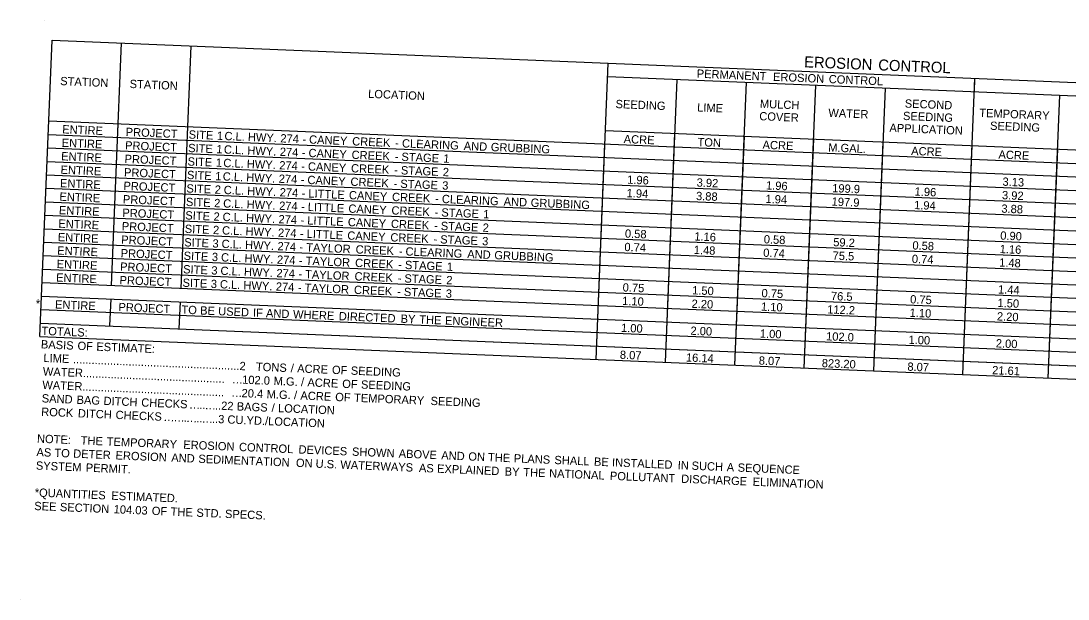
# Model space of a CAD drawing. Extents: x 1164179 to 1171425, y 1655958 to 1657208.
# Drawn here: x 1166097 to 1166854, y 1656742 to 1657160 of the extents above; entities that cross this region are included whole.
import ezdxf

# ---------------------------------------------------------------- set-up
doc = ezdxf.new("R2010")
doc.units = 0
doc.layers.add('Default', color=7, linetype='Continuous')

msp = doc.modelspace()

# ---------------------------------------------------------------- linework, layer by layer
at = {"layer": 'Default'}
for p, q in [((1166114.2, 1657160.31), (1166114.2, 1657160.31)), ((1166110.61, 1656932.12), (1166119.48, 1657146.43)), ((1166110.61, 1656932.12), (1166119.48, 1657146.43)), ((1166119.48, 1657146.43), (1167314.3, 1657097.01)), ((1166162.4, 1656969.01), (1166169.65, 1657144.36)), ((1166212.57, 1656966.93), (1166219.82, 1657142.28)), ((1166512.46, 1656915.49), (1166521.32, 1657129.81)), ((1166520.92, 1657120.07), (1167313.89, 1657087.27)), ((1166562.63, 1656913.42), (1166571.09, 1657117.99)), ((1166612.8, 1656911.34), (1166621.26, 1657115.92)), ((1166777.43, 1656904.53), (1166786.3, 1657118.85)), ((1166785.89, 1657109.11), (1166786.3, 1657118.85)), ((1166662.97, 1656909.27), (1166671.43, 1657113.84)), ((1166713.14, 1656907.19), (1166721.6, 1657111.77)), ((1166839.29, 1656901.97), (1166847.75, 1657106.55)), ((1166117.06, 1657087.98), (1167311.88, 1657038.56)), ((1166162.4, 1656969.01), (1166167.23, 1657085.91)), ((1166116.66, 1657078.24), (1167311.47, 1657028.82)), ((1166212.57, 1656966.93), (1166217.4, 1657083.83)), ((1166519.31, 1657081.1), (1167186.13, 1657053.52)), ((1166562.63, 1656913.42), (1166569.48, 1657079.03)), ((1166612.8, 1656911.34), (1166619.65, 1657076.95)), ((1166512.46, 1656915.49), (1166518.91, 1657071.36)), ((1166662.97, 1656909.27), (1166669.82, 1657074.88)), ((1166713.14, 1656907.19), (1166719.99, 1657072.8)), ((1166777.43, 1656904.53), (1166784.28, 1657070.14)), ((1166116.26, 1657068.5), (1167311.07, 1657019.07)), ((1166839.29, 1656901.97), (1166846.14, 1657067.58)), ((1166115.85, 1657058.76), (1167310.67, 1657009.33)), ((1166115.45, 1657049.02), (1167310.27, 1656999.59)), ((1166115.05, 1657039.28), (1167309.86, 1656989.85)), ((1166114.64, 1657029.53), (1167309.46, 1656980.11)), ((1166114.24, 1657019.79), (1167309.06, 1656970.37)), ((1166113.84, 1657010.05), (1167308.65, 1656960.62)), ((1166113.44, 1657000.31), (1167308.25, 1656950.88)), ((1166113.03, 1656990.57), (1167307.85, 1656941.14)), ((1166112.63, 1656980.83), (1167307.44, 1656931.4)), ((1166112.23, 1656971.08), (1167307.04, 1656921.66)), ((1166111.82, 1656961.34), (1167306.64, 1656911.92)), ((1166161.19, 1656939.78), (1166161.99, 1656959.27)), ((1166161.19, 1656939.78), (1166161.99, 1656959.27)), ((1166211.36, 1656937.71), (1166212.16, 1656957.19)), ((1166211.36, 1656937.71), (1166212.16, 1656957.19)), ((1166111.42, 1656951.6), (1167306.24, 1656902.17)), ((1166111.02, 1656941.86), (1167179.68, 1656897.65)), ((1166111.02, 1656941.86), (1167305.83, 1656892.43)), ((1166110.61, 1656932.12), (1167305.43, 1656882.69)), ((1166096.9, 1656742.22), (1166096.9, 1656742.22))]:
    msp.add_line(p, q, dxfattribs=at)

# ---------------------------------------------------------------- texts
for s, height, p in [('EROSION', 8, (1166662.7, 1657126.79)), (' CONTROL', 8, (1166713.32, 1657124.7)), ('PERMANENT', 6, (1166585.15, 1657119.29)), (' EROSION', 6, (1166638.04, 1657117.1)), ('STATION', 6, (1166125.19, 1657113.92)), ('STATION', 6, (1166175.36, 1657111.85)), (' CONTROL', 6, (1166678.33, 1657115.43)), ('LOCATION', 6, (1166347.7, 1657104.72)), ('SEEDING', 6, (1166526.48, 1657097.32)), ('LIME', 6, (1166585.45, 1657094.88)), ('MULCH', 6, (1166630.8, 1657097.51)), ('SECOND', 6, (1166735.48, 1657097.68)), ('COVER', 6, (1166630.35, 1657088.52)), ('WATER', 6, (1166680.25, 1657090.96)), ('SEEDING', 6, (1166734.22, 1657088.73)), ('TEMPORARY', 6, (1166789.31, 1657090.95)), ('ENTIRE', 6, (1166126.66, 1657079.03)), ('APPLICATION', 6, (1166724.39, 1657080.13)), ('SEEDING', 6, (1166797.11, 1657081.62)), ('PROJECT', 6, (1166172.5, 1657077.13)), ('SITE', 6, (1166218.02, 1657075.25)), (' 1', 6, (1166236.19, 1657074.5)), (' C.L.', 6, (1166241.64, 1657074.27)), (' HWY.', 6, (1166258.59, 1657073.57)), (' 274', 6, (1166282.05, 1657072.6)), (' CANEY', 6, (1166302.79, 1657071.74)), ('ACRE', 6, (1166532.38, 1657072)), ('ENTIRE', 6, (1166126.25, 1657069.29)), ('PROJECT', 6, (1166172.09, 1657067.39)), ('SITE', 6, (1166217.62, 1657065.51)), (' 1', 6, (1166235.79, 1657064.76)), (' C.L.', 6, (1166241.23, 1657064.53)), (' HWY.', 6, (1166258.18, 1657063.83)), (' -', 6, (1166297.94, 1657071.94)), (' CREEK', 6, (1166333.92, 1657070.46)), (' -', 6, (1166365.09, 1657069.17)), (' CLEARING', 6, (1166369.94, 1657068.97)), (' AND', 6, (1166414.56, 1657067.12)), (' GRUBBING', 6, (1166434.13, 1657066.31)), ('TON', 6, (1166585.7, 1657069.8)), ('ACRE', 6, (1166632.72, 1657067.85)), ('M.GAL.', 6, (1166680.18, 1657065.89)), ('ENTIRE', 6, (1166125.85, 1657059.55)), ('PROJECT', 6, (1166171.69, 1657057.65)), (' 274', 6, (1166281.65, 1657062.86)), (' -', 6, (1166297.54, 1657062.2)), (' CANEY', 6, (1166302.39, 1657062)), (' CREEK', 6, (1166333.51, 1657060.71)), (' -', 6, (1166364.69, 1657059.43)), (' STAGE', 6, (1166369.54, 1657059.22)), (' 1', 6, (1166399.81, 1657057.97)), ('ACRE', 6, (1166740.12, 1657063.41)), ('ACRE', 6, (1166803.2, 1657060.8)), ('ENTIRE', 6, (1166125.45, 1657049.81)), ('SITE', 6, (1166217.22, 1657055.77)), (' 1', 6, (1166235.39, 1657055.02)), (' C.L.', 6, (1166240.83, 1657054.79)), (' HWY.', 6, (1166257.78, 1657054.09)), (' 274', 6, (1166281.25, 1657053.12)), (' -', 6, (1166297.13, 1657052.46)), (' CANEY', 6, (1166301.98, 1657052.26)), (' CREEK', 6, (1166333.11, 1657050.97)), (' STAGE', 6, (1166369.13, 1657049.48)), ('PROJECT', 6, (1166171.29, 1657047.91)), ('SITE', 6, (1166216.81, 1657046.03)), (' 1', 6, (1166234.98, 1657045.27)), (' C.L.', 6, (1166240.43, 1657045.05)), (' HWY.', 6, (1166257.38, 1657044.35)), (' 274', 6, (1166280.84, 1657043.38)), (' CANEY', 6, (1166301.58, 1657042.52)), (' CREEK', 6, (1166332.71, 1657041.23)), (' -', 6, (1166364.28, 1657049.68)), (' 2', 6, (1166399.41, 1657048.23)), ('1.96', 6, (1166534.87, 1657042.63)), ('3.13', 6, (1166806.1, 1657041.16)), ('ENTIRE', 6, (1166125.05, 1657040.06)), ('PROJECT', 6, (1166170.89, 1657038.17)), ('SITE', 6, (1166216.41, 1657036.28)), (' 2', 6, (1166234.58, 1657035.53)), (' C.L.', 6, (1166241.12, 1657035.26)), (' HWY.', 6, (1166258.07, 1657034.56)), (' 274', 6, (1166281.54, 1657033.59)), (' -', 6, (1166296.73, 1657042.72)), (' -', 6, (1166363.88, 1657039.94)), (' STAGE', 6, (1166368.73, 1657039.74)), (' 3', 6, (1166399.01, 1657038.49)), ('3.92', 6, (1166585.08, 1657040.55)), ('1.96', 6, (1166635.21, 1657038.48)), ('199.9', 6, (1166683.05, 1657036.5)), ('1.96', 6, (1166742.61, 1657034.03)), ('ENTIRE', 6, (1166124.64, 1657030.32)), ('PROJECT', 6, (1166170.48, 1657028.43)), ('SITE', 6, (1166216.01, 1657026.54)), (' 2', 6, (1166234.18, 1657025.79)), (' -', 6, (1166297.42, 1657032.93)), (' LITTLE', 6, (1166302.28, 1657032.73)), (' CANEY', 6, (1166331.61, 1657031.52)), (' CREEK', 6, (1166362.74, 1657030.23)), (' CLEARING', 6, (1166398.76, 1657028.74)), (' AND', 6, (1166443.39, 1657026.89)), (' GRUBBING', 6, (1166462.95, 1657026.08)), ('1.94', 6, (1166534.48, 1657032.88)), ('3.88', 6, (1166584.64, 1657030.81)), ('1.94', 6, (1166634.82, 1657028.73)), ('197.9', 6, (1166682.65, 1657026.75)), ('3.92', 6, (1166805.72, 1657031.42)), ('ENTIRE', 6, (1166124.24, 1657020.58)), ('PROJECT', 6, (1166170.08, 1657018.68)), (' C.L.', 6, (1166240.72, 1657025.52)), (' HWY.', 6, (1166257.67, 1657024.82)), (' 274', 6, (1166281.13, 1657023.85)), (' -', 6, (1166297.02, 1657023.19)), (' LITTLE', 6, (1166301.87, 1657022.99)), (' CANEY', 6, (1166331.21, 1657021.78)), (' CREEK', 6, (1166362.34, 1657020.49)), (' -', 6, (1166393.91, 1657028.94)), (' STAGE', 6, (1166398.36, 1657019)), ('1.94', 6, (1166742.23, 1657024.29)), ('3.88', 6, (1166805.28, 1657021.68)), ('ENTIRE', 6, (1166123.84, 1657010.84)), ('SITE', 6, (1166215.6, 1657016.8)), (' 2', 6, (1166233.78, 1657016.05)), (' C.L.', 6, (1166240.31, 1657015.78)), (' HWY.', 6, (1166257.27, 1657015.08)), (' 274', 6, (1166280.73, 1657014.11)), (' LITTLE', 6, (1166301.47, 1657013.25)), (' CANEY', 6, (1166330.81, 1657012.03)), (' CREEK', 6, (1166361.93, 1657010.75)), (' -', 6, (1166393.51, 1657019.2)), (' 1', 6, (1166428.64, 1657017.75)), ('PROJECT', 6, (1166169.68, 1657008.94)), ('SITE', 6, (1166215.2, 1657007.06)), (' 2', 6, (1166233.37, 1657006.31)), (' C.L.', 6, (1166239.91, 1657006.04)), (' HWY.', 6, (1166256.86, 1657005.34)), (' 274', 6, (1166280.33, 1657004.36)), (' -', 6, (1166296.62, 1657013.45)), (' LITTLE', 6, (1166301.07, 1657003.51)), (' -', 6, (1166393.11, 1657009.46)), (' STAGE', 6, (1166397.96, 1657009.26)), (' 2', 6, (1166428.23, 1657008)), ('0.58', 6, (1166533.26, 1657003.66)), ('ENTIRE', 6, (1166123.43, 1657001.1)), ('PROJECT', 6, (1166169.27, 1656999.2)), ('SITE', 6, (1166214.8, 1656997.32)), (' 3', 6, (1166232.97, 1656996.57)), (' C.L.', 6, (1166239.57, 1656996.29)), (' HWY.', 6, (1166256.52, 1656995.59)), (' -', 6, (1166296.21, 1657003.71)), (' CANEY', 6, (1166330.41, 1657002.29)), (' CREEK', 6, (1166361.53, 1657001.01)), (' -', 6, (1166392.7, 1656999.72)), (' STAGE', 6, (1166397.56, 1656999.52)), (' 3', 6, (1166427.83, 1656998.26)), ('1.16', 6, (1166583.43, 1657001.58)), ('0.58', 6, (1166633.6, 1656999.51)), ('59.2', 6, (1166683.8, 1656997.43)), ('0.90', 6, (1166804.49, 1657002.2)), ('ENTIRE', 6, (1166123.03, 1656991.36)), ('PROJECT', 6, (1166168.87, 1656989.46)), (' 274', 6, (1166279.99, 1656994.62)), (' -', 6, (1166295.87, 1656993.96)), (' TAYLOR', 6, (1166300.73, 1656993.76)), (' CREEK', 6, (1166336.45, 1656992.28)), (' CLEARING', 6, (1166372.48, 1656990.79)), (' AND', 6, (1166417.1, 1656988.95)), (' GRUBBING', 6, (1166436.67, 1656988.14)), ('0.74', 6, (1166532.87, 1656993.92)), ('1.48', 6, (1166583.02, 1656991.84)), ('0.74', 6, (1166633.21, 1656989.77)), ('0.58', 6, (1166741, 1656995.07)), ('1.16', 6, (1166804.08, 1656992.46)), ('ENTIRE', 6, (1166122.63, 1656981.61)), ('SITE', 6, (1166214.39, 1656987.58)), (' 3', 6, (1166232.57, 1656986.82)), (' C.L.', 6, (1166239.17, 1656986.55)), (' HWY.', 6, (1166256.12, 1656985.85)), (' 274', 6, (1166279.58, 1656984.88)), (' -', 6, (1166295.47, 1656984.22)), (' TAYLOR', 6, (1166300.32, 1656984.02)), (' CREEK', 6, (1166336.05, 1656982.54)), (' -', 6, (1166367.63, 1656991)), (' STAGE', 6, (1166372.08, 1656981.05)), ('75.5', 6, (1166683.34, 1656987.69)), ('0.74', 6, (1166740.61, 1656985.32)), ('1.48', 6, (1166803.67, 1656982.72)), ('PROJECT', 6, (1166168.47, 1656979.72)), ('SITE', 6, (1166213.99, 1656977.83)), (' 3', 6, (1166232.16, 1656977.08)), (' C.L.', 6, (1166238.77, 1656976.81)), (' HWY.', 6, (1166255.72, 1656976.11)), (' 274', 6, (1166279.18, 1656975.14)), (' TAYLOR', 6, (1166299.92, 1656974.28)), (' CREEK', 6, (1166335.65, 1656972.8)), (' -', 6, (1166367.22, 1656981.25)), (' 1', 6, (1166402.35, 1656979.8)), ('ENTIRE', 6, (1166122.22, 1656971.87)), ('PROJECT', 6, (1166168.06, 1656969.98)), ('SITE', 6, (1166213.59, 1656968.09)), (' 3', 6, (1166231.76, 1656967.34)), (' C.L.', 6, (1166238.36, 1656967.07)), (' HWY.', 6, (1166255.32, 1656966.37)), (' 274', 6, (1166278.78, 1656965.4)), (' -', 6, (1166295.07, 1656974.48)), (' -', 6, (1166366.82, 1656971.51)), (' STAGE', 6, (1166371.67, 1656971.31)), (' 2', 6, (1166401.95, 1656970.06)), (' -', 6, (1166294.67, 1656964.74)), (' TAYLOR', 6, (1166299.52, 1656964.54)), (' CREEK', 6, (1166335.25, 1656963.06)), (' -', 6, (1166366.42, 1656961.77)), (' STAGE', 6, (1166371.27, 1656961.57)), (' 3', 6, (1166401.55, 1656960.32)), ('0.75', 6, (1166531.63, 1656964.69)), ('1.50', 6, (1166581.83, 1656962.62)), ('0.75', 6, (1166631.97, 1656960.54)), ('76.5', 6, (1166682.14, 1656958.47)), ('1.44', 6, (1166802.88, 1656963.23)), ('*', 6, (1166107.53, 1656952.96)), ('ENTIRE', 6, (1166121.42, 1656952.39)), ('PROJECT', 6, (1166167.26, 1656950.49)), ('1.10', 6, (1166531.26, 1656954.95)), ('2.20', 6, (1166581.43, 1656952.88)), ('1.10', 6, (1166631.6, 1656950.8)), ('0.75', 6, (1166739.37, 1656956.1)), ('1.50', 6, (1166802.48, 1656953.49)), ('TO', 6, (1166212.78, 1656948.61)), (' BE', 6, (1166224.04, 1656948.14)), (' USED', 6, (1166237.1, 1656947.6)), (' IF', 6, (1166262.25, 1656946.56)), (' AND', 6, (1166271.64, 1656946.17)), (' WHERE', 6, (1166291.2, 1656945.37)), (' DIRECTED', 6, (1166324.26, 1656944)), ('112.2', 6, (1166679.46, 1656948.82)), ('1.10', 6, (1166739, 1656946.36)), ('2.20', 6, (1166802.08, 1656943.75)), (' BY', 6, (1166368.96, 1656942.15)), (' THE', 6, (1166382.39, 1656941.59)), (' ENGINEER', 6, (1166401.03, 1656940.82)), ('1.00', 6, (1166530.45, 1656935.47)), ('TOTALS:', 6, (1166111.64, 1656933.28)), ('2.00', 6, (1166580.62, 1656933.39)), ('1.00', 6, (1166630.79, 1656931.32)), ('102.0', 6, (1166678.63, 1656929.34)), ('BASIS', 6, (1166111.23, 1656923.53)), (' OF', 6, (1166135.47, 1656922.53)), (' ESTIMATE:', 6, (1166149.05, 1656921.97)), ('1.00', 6, (1166738.19, 1656926.87)), ('2.00', 6, (1166801.27, 1656924.26)), (' LIME', 6, (1166110.83, 1656913.79)), ('8.07', 6, (1166529.63, 1656915.98)), ('16.14', 6, (1166577.38, 1656914.01)), (' ......................................................2', 6, (1166132.26, 1656912.91)), (' TONS', 6, (1166264.39, 1656907.44)), (' /', 6, (1166289.54, 1656906.4)), (' ACRE', 6, (1166294.2, 1656906.21)), (' OF', 6, (1166319.35, 1656905.17)), (' SEEDING', 6, (1166332.93, 1656904.61)), ('8.07', 6, (1166629.97, 1656911.83)), ('823.20', 6, (1166675.5, 1656909.95)), ('8.07', 6, (1166737.37, 1656907.39)), ('21.61', 6, (1166798.61, 1656904.86)), (' WATER..............................................', 6, (1166110.43, 1656904.05)), ('102.0', 6, (1166256.65, 1656898)), (' M.G.', 6, (1166277.2, 1656897.15)), (' WATER..............................................', 6, (1166110.03, 1656894.31)), ('…', 6, (1166249.26, 1656898.31)), (' /', 6, (1166296.94, 1656896.34)), (' ACRE', 6, (1166301.59, 1656896.14)), (' OF', 6, (1166326.75, 1656895.1)), (' SEEDING', 6, (1166340.32, 1656894.54)), (' SAND', 6, (1166109.62, 1656884.57)), (' BAG', 6, (1166134.78, 1656883.53)), (' DITCH', 6, (1166154.27, 1656882.72)), ('…', 6, (1166248.85, 1656888.57)), ('20.4', 6, (1166256.25, 1656888.26)), (' M.G.', 6, (1166272.13, 1656887.6)), (' /', 6, (1166291.87, 1656886.79)), (' ACRE', 6, (1166296.53, 1656886.59)), (' OF', 6, (1166321.68, 1656885.55)), (' TEMPORARY', 6, (1166335.26, 1656884.99)), (' SEEDING', 6, (1166390.58, 1656882.7)), (' ROCK', 6, (1166109.22, 1656874.83)), (' CHECKS', 6, (1166181.51, 1656881.59)), ('…', 6, (1166218.31, 1656880.07)), ('..', 6, (1166225.7, 1656879.77)), ('…', 6, (1166229.63, 1656879.6)), ('..22', 6, (1166237.02, 1656879.3)), (' BAGS', 6, (1166250.54, 1656878.74)), (' /', 6, (1166275.71, 1656877.7)), (' LOCATION', 6, (1166280.36, 1656877.51)), (' DITCH', 6, (1166135.73, 1656873.73)), (' CHECKS', 6, (1166162.97, 1656872.6)), ('..3', 6, (1166234.86, 1656869.63)), (' CU.YD./LOCATION', 6, (1166243.79, 1656869.26)), ('…', 6, (1166199.77, 1656871.08)), ('…', 6, (1166207.17, 1656870.77)), ('.', 6, (1166214.56, 1656870.47)), ('…', 6, (1166216.15, 1656870.4)), ('..', 6, (1166223.55, 1656870.1)), ('…', 6, (1166227.47, 1656869.93)), ('NOTE:', 6, (1166108.41, 1656855.34)), ('   THE', 6, (1166133.28, 1656854.31)), (' TEMPORARY', 6, (1166156.56, 1656853.35)), ('AS', 6, (1166108.01, 1656845.6)), (' TO', 6, (1166118.75, 1656845.16)), (' DETER', 6, (1166132.33, 1656844.6)), (' EROSION', 6, (1166211.89, 1656851.06)), (' CONTROL', 6, (1166252.16, 1656849.4)), (' DEVICES', 6, (1166295.15, 1656847.62)), (' SHOWN', 6, (1166333.81, 1656846.02)), (' ABOVE', 6, (1166367.56, 1656844.62)), (' EROSION', 6, (1166162.94, 1656843.33)), (' AND', 6, (1166203.21, 1656841.66)), (' SEDIMENTATION', 6, (1166222.78, 1656840.85)), (' ON', 6, (1166293.3, 1656837.94)), (' U.S.', 6, (1166307.5, 1656837.35)), (' WATERWAYS', 6, (1166325.39, 1656836.61)), (' AND', 6, (1166398.31, 1656843.35)), (' ON', 6, (1166417.87, 1656842.54)), (' THE', 6, (1166432.08, 1656841.95)), (' PLANS', 6, (1166450.71, 1656841.18)), (' SHALL', 6, (1166480.07, 1656839.97)), (' BE', 6, (1166508.64, 1656838.79)), (' INSTALLED', 6, (1166521.69, 1656838.25)), ('SYSTEM', 6, (1166107.61, 1656835.86)), (' PERMIT.', 6, (1166141.42, 1656834.46)), (' AS', 6, (1166382.19, 1656834.26)), (' EXPLAINED', 6, (1166395.26, 1656833.72)), (' BY', 6, (1166444.16, 1656831.7)), (' THE', 6, (1166457.6, 1656831.14)), (' NATIONAL', 6, (1166476.23, 1656830.37)), (' IN', 6, (1166569.19, 1656836.28)), (' SUCH', 6, (1166579.2, 1656835.87)), (' A', 6, (1166604.59, 1656834.82)), (' SEQUENCE', 6, (1166612.52, 1656834.49)), (' POLLUTANT', 6, (1166520.15, 1656828.55)), (' DISCHARGE', 6, (1166571.64, 1656826.42)), (' ELIMINATION', 6, (1166623.33, 1656824.28)), ('*QUANTITIES', 6, (1166106.8, 1656816.38)), (' ESTIMATED.', 6, (1166159.89, 1656814.18)), ('SEE', 6, (1166106.4, 1656806.63)), (' SECTION', 6, (1166122.72, 1656805.96)), (' 104.03', 6, (1166161.59, 1656804.35)), (' OF', 6, (1166189.14, 1656803.21)), (' THE', 6, (1166202.72, 1656802.65)), (' STD.', 6, (1166221.35, 1656801.88)), (' SPECS.', 6, (1166242.03, 1656801.02))]:
    msp.add_text(s, height=height, rotation=357.63112, dxfattribs=at).set_placement(p)

doc.saveas('drawing.dxf')
